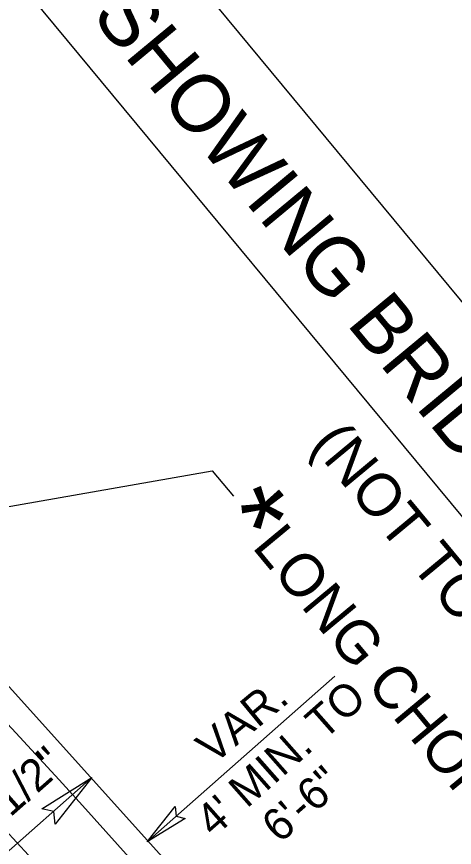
# Model space of a CAD drawing. Extents: x 2057815 to 2059783, y 687683 to 689713.
# Drawn here: x 2058305.3 to 2058376.8, y 688617 to 688752.6 of the extents above; entities that cross this region are included whole.
import ezdxf

# ---------------------------------------------------------------- set-up
doc = ezdxf.new("R2010")
doc.units = 0
for name, color, linetype in [('Prop Dimension Text', 7, 'Continuous'), ('Prop EOT', 7, 'Continuous'), ('Prop Horizontal Alignment', 7, 'Continuous'), ('Prop Roadway Bridge', 7, 'Continuous'), ('Prop Terminator CELL', 7, 'Continuous')]:
    doc.layers.add(name, color=color, linetype=linetype)

msp = doc.modelspace()

# ---------------------------------------------------------------- linework, layer by layer
at = {"layer": 'Prop Dimension Text'}
for p, q in [((2058238.89, 688838.76), (2058529.04, 688488.86)), ((2058300.68, 688672.08), (2058337.2, 688678.52)), ((2058337.2, 688678.52), (2058340.66, 688674.36)), ((2058357.23, 688645), (2058326.59, 688617.92)), ((2058285.56, 688600.17), (2058317.53, 688628.42))]:
    msp.add_line(p, q, dxfattribs=at)
msp.add_lwpolyline([(2058256.12, 688853.04), (2058546.27, 688503.15), (2058374.95, 688361.08), (2058084.8, 688710.97)], close=True, dxfattribs=at)
at = {"layer": 'Prop EOT'}
for radius, start, end in [(1012, 31.85515, 52.52584), (986, 31.84967, 52.51508)]:
    msp.add_arc((2057566.24, 687944.19), radius, start, end, dxfattribs=at)
at = {"layer": 'Prop Horizontal Alignment'}
msp.add_arc((2057566.24, 687944.19), 1000, 31.85265, 52.52094, dxfattribs=at)
at = {"layer": 'Prop Roadway Bridge'}
msp.add_line((2058276.73, 688673.54), (2058372.16, 688567.61), dxfattribs=at)
at = {"layer": 'Prop Terminator CELL'}
for points in [[(2058309.39, 688623.33), (2058317.53, 688628.42), (2058311.56, 688620.83), (2058311.34, 688622.89)], [(2058332.81, 688621.76), (2058326.59, 688617.92), (2058331.17, 688623.68), (2058331.33, 688622.11)]]:
    msp.add_lwpolyline(points, close=True, dxfattribs=at)

# ---------------------------------------------------------------- texts
at = {"layer": 'Prop Dimension Text'}
for s, height, rotation, p in [('SKETCH SHOWING BRIDGE/PAVEMENT RELATIONSHIP', 9.45, 309.6672, (2058282.36, 688794.91)), ('(NOT TO SCALE)', 7, 309.6672, (2058353.13, 688682.75)), ('*', 14, 309.6672, (2058335.39, 688668.86)), ('LONG CHORD', 7, 309.6672, (2058343.58, 688666.03)), ("4' MIN. TO", 5.25, 41.463, (2058337.46, 688618.52)), ('VAR.', 5.25, 39.605, (2058337.41, 688630.44)), ('42\'-4 1/2"', 5.25, 41.4331, (2058291.21, 688610.37)), ('6\'-6"', 5.25, 41.463, (2058348.25, 688617.55))]:
    msp.add_text(s, height=height, rotation=rotation, dxfattribs=at).set_placement(p)

doc.saveas('drawing.dxf')
